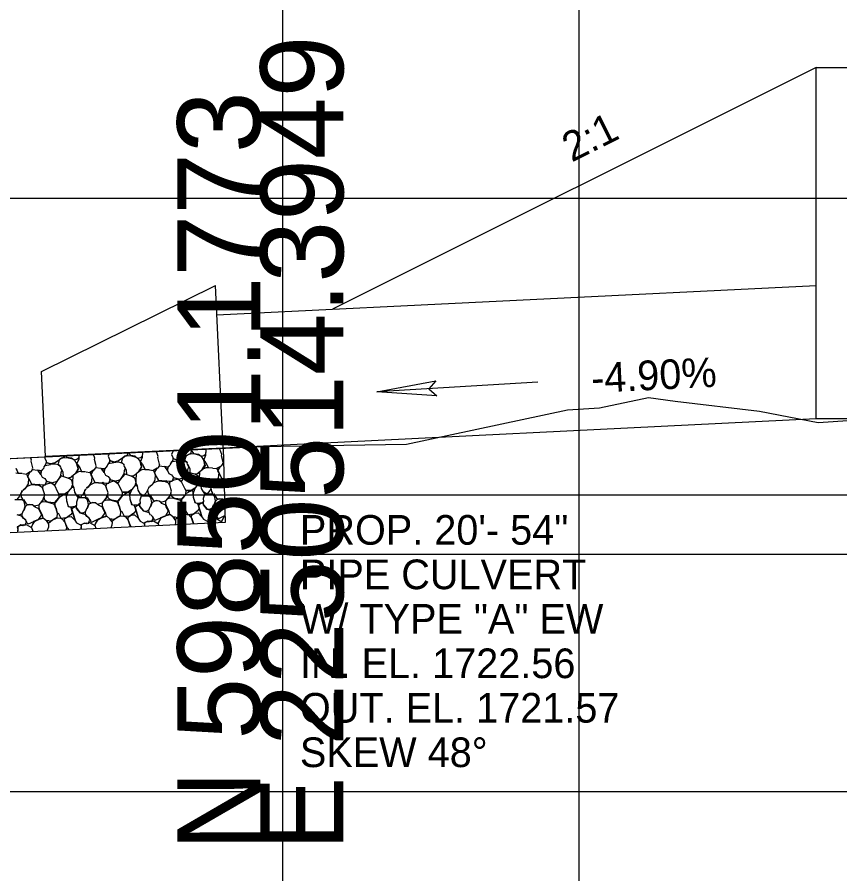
# Model space of a CAD drawing. Extents: x -63 to 277, y -62 to 156.
# Drawn here: x 48.09 to 75.84, y -10.78 to 18.11 of the extents above; entities that cross this region are included whole.
import ezdxf

# ---------------------------------------------------------------- set-up
doc = ezdxf.new("R2010")
doc.units = 0
for name, color, linetype in [('DESIGN - DRAINAGE - Cross Drains', 7, 'Continuous'), ('DESIGN - DRAINAGE - Storm Sewer', 7, 'Continuous'), ('DESIGN - DRAINAGE - Text', 7, 'Continuous'), ('DESIGN - SHEET - Light Grid', 7, 'Continuous'), ('DESIGN - SHEET - Linework', 7, 'Continuous'), ('DESIGN - TRANSPORTATION - Proposed Layout Patterning', 7, 'Continuous'), ('DESIGN - TYPICAL - Finished Grade and Subgrade', 7, 'Continuous'), ('DESIGN - TYPICAL - Finished Grade Slopes Text', 7, 'Continuous'), ('SURVEY - GROUND - Top of Ground', 7, 'Continuous')]:
    doc.layers.add(name, color=color, linetype=linetype)

msp = doc.modelspace()

# ---------------------------------------------------------------- linework, layer by layer
at = {"layer": 'DESIGN - DRAINAGE - Cross Drains'}
for p, q in [((48.907, 6.16), (54.778, 9.063)), ((55.035, 3.569), (54.778, 9.063)), ((54.825, 8.065), (75.035, 9.063)), ((75.035, 4.56), (55.035, 3.569))]:
    msp.add_line(p, q, dxfattribs=at)
msp.add_lwpolyline([(26.245, 2.183), (55.035, 3.569), (55.108, 1.07), (26.318, -0.316)], close=True, dxfattribs=at)
at = {"layer": 'DESIGN - DRAINAGE - Storm Sewer'}
msp.add_lwpolyline([(75.035, 16.413), (82.035, 16.413), (82.035, 4.56), (75.035, 4.56)], close=True, dxfattribs=at)
at = {"layer": 'DESIGN - DRAINAGE - Text'}
msp.add_line((65.655, 5.795), (60.223, 5.477), dxfattribs=at)
msp.add_lwpolyline([(60.223, 5.477), (62.215, 5.844), (61.97, 5.579), (62.244, 5.335)], close=True, dxfattribs=at)
msp.add_lwpolyline([(60.223, 5.477), (62.215, 5.844), (61.97, 5.579), (62.244, 5.335), (60.223, 5.477)], dxfattribs=at)
at = {"layer": 'DESIGN - SHEET - Light Grid'}
for p, q in [((0, 0), (56.291, 0)), ((56.291, 0), (78.789, 0))]:
    msp.add_line(p, q, dxfattribs=at)
at = {"layer": 'DESIGN - SHEET - Linework'}
for p, q in [((57.045, -58), (57.045, 152)), ((67.045, -58), (67.045, 152)), ((-42.955, 12), (257.045, 12)), ((-42.955, 2), (257.045, 2)), ((-42.955, -8), (257.045, -8))]:
    msp.add_line(p, q, dxfattribs=at)
at = {"layer": 'DESIGN - TRANSPORTATION - Proposed Layout Patterning'}
for p, q in [((49.042, 3.288), (48.907, 6.16)), ((55.035, 3.569), (49.042, 3.288))]:
    msp.add_line(p, q, dxfattribs=at)
for points in [[(53.349, 3.487), (53.299, 3.364), (53.342, 3.255), (53.339, 3.17), (53.272, 3.073), (53.263, 3.042), (53.306, 3.119), (53.49, 3.149), (53.479, 3.174), (53.348, 3.22), (53.494, 3.164), (53.559, 3.166), (53.644, 3.174), (53.75, 3.142), (53.822, 3.094), (53.828, 3.059), (53.822, 3.089), (53.755, 3.147), (53.759, 3.197), (53.79, 3.308), (53.643, 3.209), (53.494, 3.164)], [(53.958, 3.517), (53.948, 3.398), (53.864, 3.365), (53.795, 3.313), (53.854, 3.365), (53.973, 3.388), (54.084, 3.377), (54.2, 3.345), (54.286, 3.312), (54.385, 3.16), (54.403, 3.071), (54.385, 3.165), (54.457, 3.082), (54.385, 3.17), (54.455, 3.337), (54.465, 3.541)], [(54.444, 3.54), (54.456, 3.467), (54.439, 3.362), (54.386, 3.31), (54.291, 3.293), (54.204, 3.36), (54.058, 3.386), (53.96, 3.517)], [(55.032, 3.099), (54.976, 3.317), (54.989, 3.358), (54.924, 3.541), (54.889, 3.562)], [(48.615, 2.912), (48.558, 3.131), (48.572, 3.171), (48.542, 3.256)], [(49.037, 3.28), (49.02, 3.239), (49.064, 3.13), (49.061, 3.045), (48.994, 2.948), (48.985, 2.918), (49.028, 2.994), (49.212, 3.025), (49.201, 3.049), (49.07, 3.095), (49.216, 3.04), (49.281, 3.042), (49.366, 3.049), (49.472, 3.017), (49.543, 2.969), (49.549, 2.934), (49.544, 2.964), (49.477, 3.022), (49.48, 3.072), (49.512, 3.183), (49.365, 3.084), (49.216, 3.04)], [(49.673, 3.311), (49.67, 3.273), (49.586, 3.241), (49.517, 3.189), (49.576, 3.24), (49.695, 3.264), (49.805, 3.252), (49.921, 3.22), (50.007, 3.188), (50.107, 3.036), (50.124, 2.946), (50.107, 3.041), (50.179, 2.958), (50.106, 3.046), (50.177, 3.213), (50.183, 3.335)], [(50.177, 3.335), (50.161, 3.237), (50.107, 3.186), (50.013, 3.168), (49.926, 3.235), (49.78, 3.261), (49.741, 3.314)], [(50.754, 2.974), (50.697, 3.193), (50.711, 3.233), (50.667, 3.358)], [(51.193, 3.384), (51.159, 3.301), (51.203, 3.193), (51.2, 3.107), (51.133, 3.01), (51.124, 2.98), (51.167, 3.056), (51.351, 3.087), (51.34, 3.112), (51.209, 3.158), (51.355, 3.102), (51.42, 3.104), (51.505, 3.111), (51.611, 3.079), (51.683, 3.031), (51.689, 2.997), (51.683, 3.026), (51.616, 3.085), (51.62, 3.135), (51.651, 3.246), (51.504, 3.146), (51.355, 3.102)], [(51.816, 3.414), (51.809, 3.335), (51.725, 3.303), (51.656, 3.251), (51.715, 3.303), (51.834, 3.326), (51.944, 3.314), (52.06, 3.283), (52.146, 3.25), (52.246, 3.098), (52.263, 3.008), (52.246, 3.103), (52.318, 3.02), (52.246, 3.108), (52.316, 3.275), (52.324, 3.438)], [(52.311, 3.437), (52.317, 3.405), (52.3, 3.3), (52.247, 3.248), (52.152, 3.23), (52.065, 3.298), (51.919, 3.324), (51.85, 3.415)], [(52.893, 3.037), (52.837, 3.255), (52.85, 3.296), (52.792, 3.461)], [(48.275, 2.717), (48.406, 2.696), (48.443, 2.622), (48.529, 2.77), (48.401, 2.696), (48.563, 2.791), (48.607, 2.847), (48.61, 2.892), (48.601, 2.857), (48.777, 2.832), (48.876, 2.69), (48.908, 2.811), (48.777, 2.827), (48.908, 2.806), (48.995, 2.913), (48.898, 2.81), (48.886, 2.69), (48.929, 2.596), (49.02, 2.554), (49.083, 2.461), (49.036, 2.344), (49.106, 2.376), (49.21, 2.404), (49.214, 2.414), (49.068, 2.455), (49.26, 2.401), (49.438, 2.456), (49.588, 2.635), (49.548, 2.644), (49.347, 2.328), (49.225, 2.41), (49.347, 2.323), (49.454, 2.101), (49.496, 2.017), (49.489, 1.907), (49.642, 2.002), (49.696, 2.028), (49.809, 2.102), (49.681, 2.023), (49.496, 2.022), (49.647, 2.002), (49.726, 2.019), (49.738, 1.944), (49.752, 1.805), (49.808, 1.611), (49.899, 1.589), (49.926, 1.515), (49.94, 1.39), (49.887, 1.323), (49.803, 1.261), (49.735, 1.219), (49.575, 1.204), (49.49, 1.362), (49.45, 1.386), (49.41, 1.535), (49.368, 1.599), (49.366, 1.683), (49.354, 1.738), (49.495, 1.902), (49.369, 1.734), (49.325, 1.727), (49.139, 1.757), (49.093, 1.766), (49.027, 1.819), (48.998, 1.933), (49.021, 2.004), (48.956, 2.197), (48.962, 2.312), (49.042, 2.334), (48.887, 2.325), (48.836, 2.348), (48.802, 2.332), (48.586, 2.356), (48.47, 2.568), (48.438, 2.627), (48.47, 2.563), (48.455, 2.372), (48.36, 2.214), (48.287, 2.157), (48.365, 2.22), (48.433, 2.287), (48.571, 2.351), (48.807, 2.328), (48.908, 2.275), (48.951, 2.197)], [(50.399, 2.779), (50.269, 2.78), (50.189, 2.948), (50.264, 2.78), (50.179, 2.788), (50.056, 2.724), (50.142, 2.872), (50.13, 2.936), (50.147, 2.867), (50.056, 2.714), (49.963, 2.641), (49.954, 2.431), (49.944, 2.271), (49.813, 2.117), (49.744, 1.935), (49.753, 1.8), (49.813, 1.616), (49.889, 1.584), (49.931, 1.51), (50.042, 1.143), (49.926, 1.51), (49.984, 1.571), (50.048, 1.603), (49.884, 1.589), (50.058, 1.604), (50.1, 1.535), (50.215, 1.393), (50.396, 1.338), (50.438, 1.265), (50.396, 1.333), (50.394, 1.423), (50.436, 1.535), (50.384, 1.423), (50.3, 1.381), (50.225, 1.383), (50.09, 1.54), (50.092, 1.64), (50.048, 1.613), (50.107, 1.64), (50.099, 1.765), (50.145, 1.901), (50.235, 1.909), (50.37, 1.908), (50.436, 1.87), (50.39, 1.903), (50.414, 1.929), (50.377, 1.988), (50.359, 2.103), (50.387, 2.178), (50.411, 2.204), (50.392, 2.184), (50.344, 2.092), (50.307, 2.016), (50.215, 1.908), (50.098, 1.975), (50.145, 1.906), (50.098, 1.98), (50.029, 2.093), (50.01, 2.232), (49.94, 2.25), (49.938, 2.305), (49.978, 2.292), (50.005, 2.232), (49.973, 2.291), (49.933, 2.49), (49.81, 2.567), (49.89, 2.589), (49.939, 2.631), (49.964, 2.626), (49.929, 2.625), (49.89, 2.579), (49.8, 2.567), (49.593, 2.631), (49.558, 2.644), (49.575, 2.76), (49.603, 2.811), (49.56, 2.915), (49.629, 2.767), (49.639, 2.622)], [(50.414, 2.779), (50.545, 2.758), (50.582, 2.684), (50.668, 2.832), (50.54, 2.758), (50.702, 2.853), (50.746, 2.909), (50.749, 2.954), (50.74, 2.919), (50.916, 2.894), (51.015, 2.752), (51.047, 2.873), (50.916, 2.889), (51.047, 2.868), (51.134, 2.976), (51.037, 2.873), (51.025, 2.752), (51.068, 2.658), (51.159, 2.616), (51.222, 2.523), (51.176, 2.406), (51.245, 2.438), (51.349, 2.467), (51.354, 2.477), (51.207, 2.517), (51.399, 2.463), (51.577, 2.518), (51.727, 2.698), (51.687, 2.706), (51.486, 2.391), (51.364, 2.472), (51.486, 2.386), (51.593, 2.164), (51.635, 2.08), (51.628, 1.969), (51.781, 2.064), (51.835, 2.091), (51.948, 2.164), (51.82, 2.085), (51.635, 2.085), (51.786, 2.064), (51.865, 2.081), (51.877, 2.007), (51.892, 1.867), (51.947, 1.674), (52.038, 1.651), (52.065, 1.577), (52.079, 1.452), (52.026, 1.386), (51.942, 1.323), (51.874, 1.281), (51.714, 1.267), (51.629, 1.424), (51.589, 1.448), (51.549, 1.597), (51.507, 1.661), (51.505, 1.746), (51.493, 1.8), (51.634, 1.965), (51.508, 1.796), (51.464, 1.79), (51.278, 1.819), (51.232, 1.828), (51.166, 1.881), (51.138, 1.995), (51.16, 2.066), (51.095, 2.259), (51.101, 2.374), (51.181, 2.397), (51.026, 2.387), (50.975, 2.411), (50.941, 2.395), (50.725, 2.418), (50.609, 2.63), (50.577, 2.689), (50.609, 2.625), (50.594, 2.435), (50.499, 2.277), (50.426, 2.22), (50.504, 2.282), (50.572, 2.349), (50.71, 2.413), (50.946, 2.39), (51.047, 2.338), (51.09, 2.259)], [(52.538, 2.841), (52.408, 2.843), (52.328, 3.01), (52.403, 2.842), (52.318, 2.85), (52.195, 2.786), (52.281, 2.934), (52.269, 2.999), (52.286, 2.929), (52.195, 2.776), (52.102, 2.704), (52.093, 2.493), (52.083, 2.333), (51.953, 2.179), (51.883, 1.997), (51.892, 1.862), (51.952, 1.679), (52.028, 1.646), (52.07, 1.572), (52.181, 1.205), (52.065, 1.572), (52.123, 1.634), (52.188, 1.666), (52.023, 1.651), (52.198, 1.666), (52.24, 1.597), (52.354, 1.455), (52.535, 1.401), (52.578, 1.327), (52.536, 1.396), (52.533, 1.486), (52.575, 1.597), (52.523, 1.485), (52.439, 1.443), (52.364, 1.446), (52.229, 1.602), (52.232, 1.702), (52.187, 1.676), (52.246, 1.702), (52.238, 1.827), (52.284, 1.964), (52.374, 1.971), (52.509, 1.97), (52.575, 1.932), (52.529, 1.966), (52.553, 1.991), (52.516, 2.05), (52.498, 2.165), (52.526, 2.241), (52.55, 2.266), (52.531, 2.246), (52.483, 2.154), (52.446, 2.078), (52.354, 1.971), (52.237, 2.037), (52.284, 1.969), (52.237, 2.042), (52.168, 2.155), (52.149, 2.295), (52.079, 2.313), (52.077, 2.368), (52.117, 2.354), (52.144, 2.295), (52.112, 2.354), (52.072, 2.553), (51.949, 2.629), (52.029, 2.651), (52.078, 2.693), (52.103, 2.689), (52.068, 2.688), (52.029, 2.641), (51.939, 2.629), (51.732, 2.693), (51.697, 2.707), (51.714, 2.822), (51.742, 2.873), (51.699, 2.977), (51.769, 2.829), (51.778, 2.684)], [(52.553, 2.842), (52.684, 2.821), (52.721, 2.747), (52.807, 2.894), (52.679, 2.82), (52.841, 2.915), (52.885, 2.971), (52.889, 3.017), (52.88, 2.981), (53.055, 2.956), (53.155, 2.814), (53.186, 2.935), (53.055, 2.951), (53.186, 2.93), (53.273, 3.038), (53.176, 2.935), (53.165, 2.815), (53.207, 2.721), (53.299, 2.678), (53.361, 2.585), (53.315, 2.469), (53.384, 2.501), (53.488, 2.529), (53.493, 2.539), (53.346, 2.58), (53.538, 2.525), (53.717, 2.581), (53.866, 2.76), (53.826, 2.769), (53.625, 2.453), (53.503, 2.534), (53.625, 2.448), (53.732, 2.226), (53.774, 2.142), (53.768, 2.032), (53.92, 2.126), (53.974, 2.153), (54.087, 2.226), (53.959, 2.147), (53.774, 2.147), (53.925, 2.126), (54.004, 2.144), (54.017, 2.069), (54.031, 1.929), (54.086, 1.736), (54.177, 1.714), (54.204, 1.639), (54.218, 1.515), (54.165, 1.448), (54.081, 1.386), (54.013, 1.344), (53.853, 1.329), (53.768, 1.487), (53.728, 1.51), (53.688, 1.659), (53.646, 1.723), (53.644, 1.808), (53.632, 1.863), (53.773, 2.027), (53.648, 1.858), (53.603, 1.852), (53.417, 1.881), (53.372, 1.89), (53.305, 1.943), (53.277, 2.057), (53.3, 2.128), (53.234, 2.321), (53.241, 2.437), (53.32, 2.459), (53.165, 2.449), (53.114, 2.473), (53.08, 2.457), (52.864, 2.481), (52.748, 2.692), (52.716, 2.751), (52.748, 2.687), (52.734, 2.497), (52.638, 2.339), (52.565, 2.282), (52.643, 2.344), (52.711, 2.411), (52.849, 2.475), (53.085, 2.452), (53.187, 2.4), (53.229, 2.321)], [(54.678, 2.904), (54.547, 2.905), (54.468, 3.073), (54.542, 2.905), (54.457, 2.912), (54.334, 2.849), (54.42, 2.996), (54.408, 3.061), (54.425, 2.991), (54.334, 2.839), (54.241, 2.766), (54.233, 2.556), (54.222, 2.395), (54.092, 2.241), (54.022, 2.059), (54.031, 1.924), (54.091, 1.741), (54.167, 1.708), (54.209, 1.634), (54.32, 1.268), (54.204, 1.634), (54.263, 1.696), (54.327, 1.728), (54.162, 1.713), (54.337, 1.728), (54.379, 1.659), (54.493, 1.518), (54.674, 1.463), (54.717, 1.389), (54.675, 1.458), (54.672, 1.548), (54.714, 1.659), (54.662, 1.548), (54.578, 1.505), (54.503, 1.508), (54.369, 1.664), (54.371, 1.764), (54.326, 1.738), (54.386, 1.765), (54.377, 1.889), (54.423, 2.026), (54.513, 2.033), (54.648, 2.032), (54.714, 1.994), (54.668, 2.028), (54.692, 2.054), (54.656, 2.113), (54.637, 2.227), (54.665, 2.303), (54.689, 2.329), (54.67, 2.308), (54.623, 2.217), (54.585, 2.141), (54.493, 2.033), (54.376, 2.099), (54.423, 2.031), (54.376, 2.104), (54.307, 2.218), (54.288, 2.357), (54.218, 2.375), (54.216, 2.43), (54.257, 2.416), (54.283, 2.357), (54.252, 2.416), (54.211, 2.615), (54.088, 2.691), (54.168, 2.714), (54.217, 2.755), (54.242, 2.751), (54.207, 2.75), (54.168, 2.704), (54.078, 2.691), (53.872, 2.755), (53.836, 2.769), (53.853, 2.885), (53.881, 2.935), (53.838, 3.039), (53.908, 2.891), (53.917, 2.746)], [(54.693, 2.904), (54.823, 2.883), (54.86, 2.809), (54.946, 2.956), (54.818, 2.883), (54.981, 2.977), (55.024, 3.034), (55.028, 3.079), (55.019, 3.044), (55.05, 3.039)], [(48.26, 2.717), (48.13, 2.718), (48.05, 2.886), (48.125, 2.718), (48.04, 2.725)], [(55.065, 2.536), (55.003, 2.543), (54.887, 2.755), (54.855, 2.814), (54.887, 2.75), (54.873, 2.559), (54.777, 2.401), (54.704, 2.344), (54.782, 2.406), (54.85, 2.473), (54.988, 2.538), (55.065, 2.53)], [(48.006, 1.839), (48.096, 1.847), (48.231, 1.846), (48.297, 1.807), (48.251, 1.841), (48.275, 1.867), (48.238, 1.926), (48.22, 2.04), (48.248, 2.116), (48.272, 2.142), (48.253, 2.121), (48.205, 2.03), (48.167, 1.954), (48.076, 1.846)], [(52.876, 0.962), (52.857, 1.015), (52.684, 1.115), (52.604, 1.098), (52.649, 1.109), (52.643, 1.134), (52.671, 1.194), (52.686, 1.195), (52.659, 1.274), (52.593, 1.327), (52.649, 1.274), (52.696, 1.195), (52.702, 1.165), (52.748, 1.142), (52.931, 1.227), (53.104, 1.297), (52.936, 1.212), (52.898, 1.141), (52.846, 1.04), (52.898, 1.136), (52.931, 1.212), (52.93, 1.232), (53.098, 1.307), (53.194, 1.455), (53.12, 1.598), (53.103, 1.647), (52.972, 1.708), (52.93, 1.747), (52.884, 1.791), (52.779, 1.803), (52.729, 1.786), (52.645, 1.744), (52.59, 1.597), (52.636, 1.739), (52.601, 1.898), (52.575, 1.927), (52.605, 1.928), (52.584, 1.967), (52.673, 1.82), (52.734, 1.792), (52.784, 1.803), (52.879, 1.796), (52.94, 1.753), (53.109, 1.792), (53.23, 1.946), (53.267, 2.047), (53.23, 1.946), (53.152, 1.859), (53.094, 1.792), (53.092, 1.697), (53.114, 1.638), (53.209, 1.445), (53.232, 1.341), (53.104, 1.302), (53.257, 1.342), (53.355, 1.254), (53.428, 1.137), (53.426, 1.036), (53.406, 0.988)], [(55.087, 1.793), (55.07, 1.81), (55.023, 1.853), (54.918, 1.865), (54.868, 1.849), (54.785, 1.806), (54.729, 1.66), (54.775, 1.801), (54.74, 1.96), (54.714, 1.989), (54.744, 1.99), (54.723, 2.03), (54.812, 1.882), (54.873, 1.854), (54.923, 1.865), (55.018, 1.858), (55.079, 1.815), (55.086, 1.816)], [(48.626, 0.758), (48.579, 0.89), (48.406, 0.99), (48.326, 0.973), (48.371, 0.984), (48.365, 1.009), (48.393, 1.07), (48.408, 1.07), (48.381, 1.15), (48.314, 1.203), (48.371, 1.149), (48.418, 1.071), (48.424, 1.041), (48.47, 1.017), (48.652, 1.102), (48.825, 1.173), (48.658, 1.088), (48.62, 1.017), (48.568, 0.915), (48.62, 1.012), (48.653, 1.087), (48.652, 1.107), (48.82, 1.182), (48.916, 1.33), (48.842, 1.473), (48.825, 1.523), (48.693, 1.584), (48.652, 1.623), (48.606, 1.666), (48.501, 1.678), (48.451, 1.662), (48.367, 1.619), (48.312, 1.473), (48.357, 1.614), (48.323, 1.773), (48.297, 1.802), (48.327, 1.803), (48.306, 1.843), (48.395, 1.695), (48.456, 1.667), (48.506, 1.678), (48.601, 1.671), (48.662, 1.628), (48.831, 1.668), (48.952, 1.822), (48.989, 1.923), (48.952, 1.822), (48.874, 1.734), (48.816, 1.667), (48.814, 1.572), (48.836, 1.513), (48.931, 1.321), (48.954, 1.216), (48.825, 1.178), (48.979, 1.217), (49.077, 1.13), (49.15, 1.012), (49.148, 0.912), (49.094, 0.78)], [(48.889, 1.75), (48.978, 1.772), (49.078, 1.765), (49.31, 1.697), (49.368, 1.614), (49.435, 1.38), (49.424, 1.23), (49.311, 1.172), (49.277, 1.141), (49.145, 1.037), (49.077, 1.13), (49.142, 1.132), (49.192, 1.113), (49.267, 1.14), (49.439, 1.225), (49.545, 1.214), (49.6, 1.195), (49.698, 1.083), (49.753, 0.939), (49.742, 0.811)], [(50.751, 0.86), (50.718, 0.953), (50.545, 1.053), (50.465, 1.035), (50.51, 1.047), (50.504, 1.071), (50.532, 1.132), (50.547, 1.133), (50.52, 1.212), (50.453, 1.265), (50.51, 1.212), (50.557, 1.133), (50.563, 1.103), (50.609, 1.079), (50.792, 1.165), (50.965, 1.235), (50.797, 1.15), (50.759, 1.079), (50.707, 0.977), (50.759, 1.074), (50.792, 1.15), (50.791, 1.17), (50.959, 1.245), (51.055, 1.393), (50.981, 1.535), (50.964, 1.585), (50.833, 1.646), (50.791, 1.685), (50.745, 1.729), (50.64, 1.741), (50.59, 1.724), (50.506, 1.682), (50.451, 1.535), (50.497, 1.676), (50.462, 1.835), (50.436, 1.865), (50.466, 1.866), (50.445, 1.905), (50.534, 1.758), (50.595, 1.729), (50.645, 1.741), (50.74, 1.734), (50.801, 1.69), (50.97, 1.73), (51.091, 1.884), (51.128, 1.985), (51.091, 1.884), (51.013, 1.796), (50.955, 1.73), (50.953, 1.635), (50.975, 1.575), (51.07, 1.383), (51.093, 1.279), (50.964, 1.24), (51.118, 1.279), (51.216, 1.192), (51.289, 1.074), (51.287, 0.974), (51.25, 0.884)], [(51.028, 1.812), (51.117, 1.835), (51.217, 1.827), (51.45, 1.759), (51.507, 1.676), (51.574, 1.443), (51.563, 1.292), (51.45, 1.234), (51.416, 1.203), (51.284, 1.099), (51.216, 1.192), (51.281, 1.194), (51.331, 1.175), (51.406, 1.203), (51.578, 1.288), (51.684, 1.276), (51.739, 1.257), (51.838, 1.145), (51.892, 1.002), (51.884, 0.914)], [(53.167, 1.874), (53.256, 1.897), (53.357, 1.89), (53.589, 1.821), (53.646, 1.738), (53.713, 1.505), (53.702, 1.355), (53.589, 1.296), (53.555, 1.265), (53.423, 1.161), (53.355, 1.254), (53.42, 1.256), (53.471, 1.238), (53.545, 1.265), (53.717, 1.35), (53.823, 1.338), (53.878, 1.32), (53.977, 1.207), (54.031, 1.064), (54.027, 1.018)], [(48.076, 1.331), (48.257, 1.276), (48.299, 1.202), (48.257, 1.271), (48.255, 1.361), (48.297, 1.472), (48.245, 1.361), (48.161, 1.318), (48.086, 1.321)], [(49.838, 0.816), (49.753, 0.929), (49.693, 1.098), (49.69, 1.188), (49.808, 1.261), (49.913, 1.264), (50.032, 1.148), (50.094, 1.054), (50.222, 0.983)], [(51.948, 0.918), (51.892, 0.992), (51.832, 1.16), (51.829, 1.25), (51.947, 1.323), (52.052, 1.327), (52.171, 1.21), (52.234, 1.117), (52.361, 1.045)], [(54.057, 1.019), (54.031, 1.054), (53.971, 1.222), (53.969, 1.312), (54.086, 1.386), (54.191, 1.389), (54.31, 1.272), (54.373, 1.179), (54.5, 1.108)], [(54.535, 1.042), (54.539, 1.124), (54.628, 1.166), (54.693, 1.158), (54.733, 1.179), (54.708, 1.159), (54.633, 1.172), (54.549, 1.124), (54.51, 1.108), (54.521, 1.041)], [(55, 1.064), (54.996, 1.077), (54.823, 1.177), (54.743, 1.16), (54.788, 1.171), (54.782, 1.196), (54.811, 1.257), (54.826, 1.257), (54.798, 1.336), (54.732, 1.39), (54.788, 1.336), (54.836, 1.258), (54.841, 1.228), (54.887, 1.204), (55.07, 1.289), (55.101, 1.302)], [(55.101, 1.288), (55.075, 1.274), (55.037, 1.203), (54.985, 1.102), (55.037, 1.198), (55.07, 1.274), (55.07, 1.294), (55.101, 1.308)], [(48.112, 0.733), (48.122, 0.937), (48.211, 0.98), (48.276, 0.971), (48.315, 0.993), (48.291, 0.972), (48.216, 0.985), (48.132, 0.937), (48.092, 0.921), (48.111, 0.817), (48.097, 0.732)], [(50.253, 0.836), (50.261, 0.999), (50.35, 1.042), (50.415, 1.034), (50.455, 1.055), (50.43, 1.034), (50.355, 1.047), (50.271, 1), (50.232, 0.983), (50.25, 0.879), (50.243, 0.835)], [(52.394, 0.939), (52.4, 1.062), (52.489, 1.104), (52.554, 1.096), (52.594, 1.117), (52.569, 1.096), (52.494, 1.109), (52.41, 1.062), (52.371, 1.046), (52.389, 0.941), (52.388, 0.939)]]:
    msp.add_lwpolyline(points, dxfattribs=at)
at = {"layer": 'DESIGN - TYPICAL - Finished Grade and Subgrade'}
msp.add_line((75.035, 16.413), (58.724, 8.258), dxfattribs=at)
at = {"layer": 'SURVEY - GROUND - Top of Ground'}
msp.add_lwpolyline([(0, 0.92), (56.291, 3.629), (61.216, 3.709), (66.653, 4.871), (67.734, 4.932), (69.389, 5.287), (70.286, 5.162), (73.125, 4.822), (75.107, 4.442), (78.789, 4.685)], dxfattribs=at)

# ---------------------------------------------------------------- texts
at = {"layer": 'DESIGN - DRAINAGE - Text'}
msp.add_text('-4.90%', height=1, rotation=2.8258, dxfattribs=at).set_placement((67.471, 5.436))
for s, p in [('PROP. 20\'- 54" ', (57.626, 0.318)), ('PIPE CULVERT', (57.626, -1.182)), ('W/ TYPE "A" EW', (57.626, -2.682)), ('IN. EL. 1722.56', (57.626, -4.182)), ('OUT. EL. 1721.57', (57.626, -5.682)), ('SKEW 48°', (57.626, -7.182))]:
    msp.add_text(s, height=1, dxfattribs=at).set_placement(p)
at = {"layer": 'DESIGN - SHEET - Light Grid'}
for s, p in [('E 2250514.3949', (59.091, -10)), ('N 598501.1773', (56.291, -10))]:
    msp.add_text(s, height=2.8, rotation=90, dxfattribs=at).set_placement(p)
at = {"layer": 'DESIGN - TYPICAL - Finished Grade Slopes Text'}
msp.add_text('2:1', height=1, rotation=26.5651, dxfattribs=at).set_placement((66.798, 13.202))

doc.saveas('drawing.dxf')
